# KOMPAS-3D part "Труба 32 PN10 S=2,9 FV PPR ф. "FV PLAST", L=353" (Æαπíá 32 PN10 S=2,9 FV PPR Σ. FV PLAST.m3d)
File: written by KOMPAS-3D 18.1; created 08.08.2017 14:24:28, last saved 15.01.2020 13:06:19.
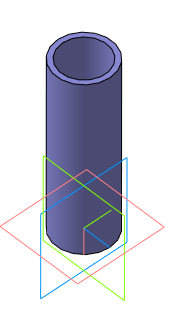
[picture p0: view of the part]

Document properties: Автор: Мирончук; Организация: Мирончук; Полное имя файла: D:\Magna\Магна Ins\Магна ins 10\М10-00.00.000\3Д\Труба 32 PN10 S=2,9 FV PPR ф. FV PLAST.m3d

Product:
- Part/product: Труба 32 PN10 S=2,9 FV PPR ф. "FV PLAST"  | designation L=353
    Материал: Труба 32 PN10 S=2,9 FV PPR ф. "FV PLAST" (density 0 kg/m3)
    Раздел спецификации: Материалы
    Примечание: м
- Part/product: Труба 32 PN10 S=2,9 FV PPR ф. "FV PLAST"
    Материал: Труба 32 PN10 S=2,9 FV PPR ф. "FV PLAST" (density 0 kg/m3)
    Раздел спецификации: Материалы
    Примечание: м
- Part/product: Труба 32 PN16 ПВХ  | designation 01
    Материал: Труба 32 PN10 НПВХ (density 0 kg/m3)
    Раздел спецификации: Материалы
    Примечание: м
  - Body: Тело 3
      Масса: 0.0238607
- Part/product: Труба 32 PN10 S=2,9 FV PPR ф. "FV PLAST"  | designation L=403
    Материал: Труба 32 PN10 S=2,9 FV PPR ф. "FV PLAST" (density 0 kg/m3)
    Раздел спецификации: Материалы
    Примечание: м
- Part/product: Труба 32 PN10 S=2,9 FV PPR ф. "FV PLAST"  | designation L=453
    Материал: Труба 32 PN10 S=2,9 FV PPR ф. "FV PLAST" (density 0 kg/m3)
    Раздел спецификации: Материалы
    Примечание: м

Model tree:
1. Эскиз:1
2. Операция выдавливания:1  (labels: Труба 32 PN10 S=2,9 FV PPR ф. "FV PLAST"; Труба 32 PN10 НПВХ)

Expressions: D-2*S

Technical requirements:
  Gost Type A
